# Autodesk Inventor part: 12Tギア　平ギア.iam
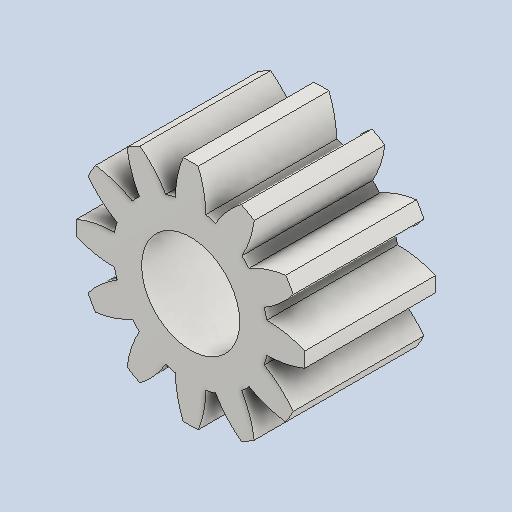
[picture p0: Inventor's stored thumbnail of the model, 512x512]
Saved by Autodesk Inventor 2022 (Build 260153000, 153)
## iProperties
Created: 2024-11
Part Number: 12Tギア　平ギア.iam
Material: Steel
Document SubType Name: Modeling
Designer: neo09
Categories: <?xml version="1.0" encoding="UTF-16"?> <MemberInstance><Categories><FamilyTemplate><FamilyTemplateParameter ValueType="xs:double" Id="1" ObjectReferenceKey="da
Density: 1 g/cm^3
Appearance: Steel
Author: neo09
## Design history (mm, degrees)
sketch "Sketch1"
  geometry: C1 r 3.5 at (0, 0)
  constraints: 1 centre point
  dimensions: "d0" = 7 diameter of C1 (= da_da)
extrude "Extrusion1" new body sketch "Sketch1" distance "d1" = 4 (= da_b); taper "d2" = 0 deg
workplane "Work Plane2"
sketch "Sketch2"
  geometry: C1 r 3.5 at (0, 0) reference; C2 r 3 at (0, 0)
  constraints: 1 centre point, 1 coincident
  dimensions: "d3" = 6 diameter of C2 (= da_d)
feature "ピッチ円直径" sketch "Sketch2" dims "d4" = 10, "d5" = 0
workplane "Work Plane8"
workplane "Work Plane9"
feature "平歯車" dims "da_b" = 4, "da_d" = 6, "da_aw" = 17.25, "da_da" = 7, "da_df" = 4.75, "da_dw" = 6, angle "da_beta" = 0 deg, "da_lefttooth" = 0, "da_righttooth" = 0
sketch "スケッチ3"
  geometry: C1 r 1.5 at (0, 0); 1 further point
  constraints: 1 centre point, 1 coincident
  dimensions: "d49" = 3 diameter of C1
extrude "押し出し2" cut sketch "スケッチ3" distance "d50" = 10; taper "d51" = 0 deg
body "Solid1"
body "Srf1"
other parameters: "d16" = 17.25 (= da_aw), "d17" = 0, "d34" = 15 deg (computed from da_z), "d39" = 0, "d41" = 0, "d43" = 17.25 (= da_aw), "d46" = 17.25 (= da_aw), "d47" = 0, "d48" = 0
